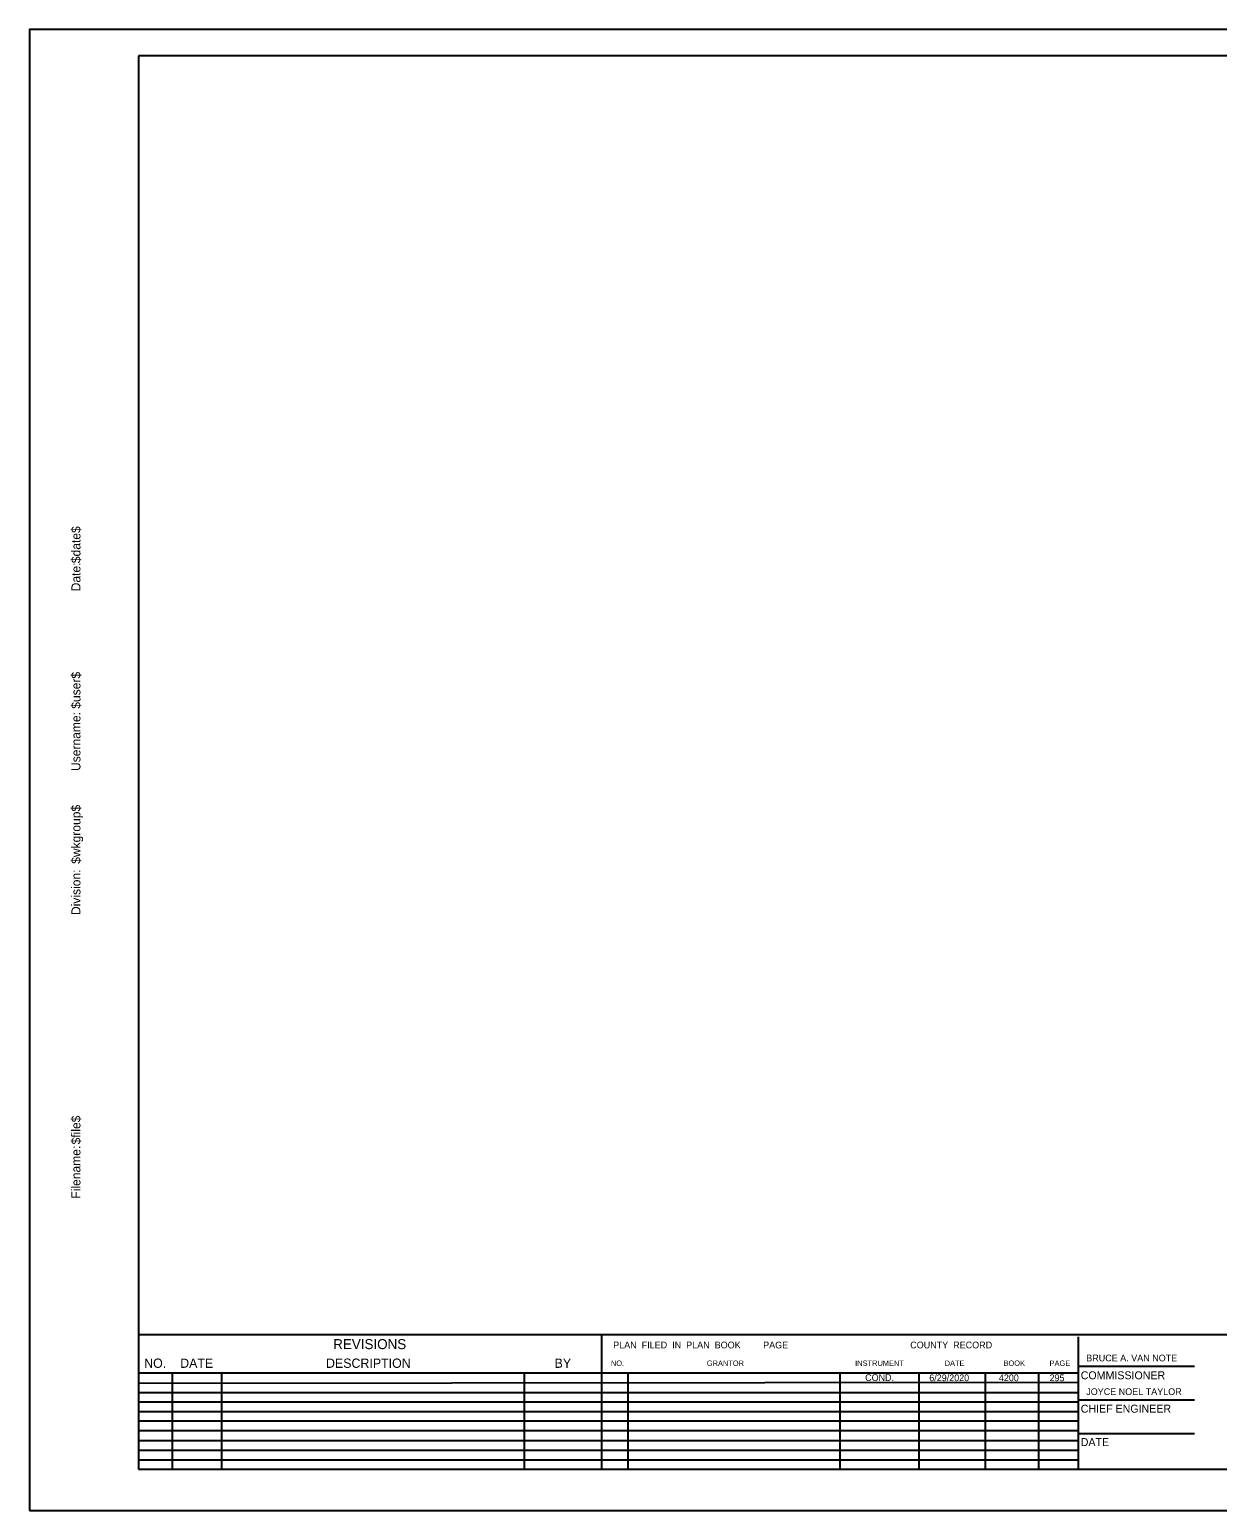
# Model space of a CAD drawing. Extents: x -415 to 435, y -303 to 247.
# Drawn here: x -415 to 26, y -303 to 247 of the extents above; entities that cross this region are included whole.
import ezdxf

# ---------------------------------------------------------------- set-up
doc = ezdxf.new("R2010")
doc.units = 0
for name, color, linetype in [('Border', 7, 'Continuous'), ('EX ROW NOTES', 7, 'Continuous'), ('PLOT BOUNDARY', 7, 'Continuous')]:
    doc.layers.add(name, color=color, linetype=linetype)

msp = doc.modelspace()

# ---------------------------------------------------------------- linework, layer by layer
at = {"layer": 'Border'}
for p, q in [((425, 237.5), (-375, 237.5)), ((-375, 237.5), (-375, -287.5)), ((-375, -237.49), (425, -237.49)), ((-202.99, -237.49), (-202.99, -287.5)), ((-25.83, -238.29), (-25.83, -287.5)), ((-375, -251.67), (-25.83, -251.67)), ((-362.5, -251.67), (-362.5, -287.5)), ((-344.13, -251.67), (-344.13, -287.5)), ((-231.63, -251.67), (-231.63, -287.5)), ((-193.15, -251.67), (-193.15, -287.5)), ((-114.41, -251.67), (-114.41, -287.5)), ((-84.88, -287.5), (-84.88, -251.67)), ((-60.27, -287.5), (-60.27, -251.67)), ((-40.59, -251.67), (-40.59, -287.5)), ((-25.83, -249.2), (17.41, -249.2)), ((-375, -255.6), (-25.83, -255.22)), ((-375, -258.96), (-25.83, -258.96)), ((-375, -262.5), (-26.02, -262.5)), ((-25.83, -261.7), (17.41, -261.7)), ((-375, -266.04), (-25.83, -266.04)), ((-375, -269.59), (-25.83, -269.59)), ((-375, -273.13), (-25.63, -273.13)), ((-25.83, -274.2), (17.41, -274.2)), ((-375, -276.87), (-25.83, -276.87)), ((-375, -280.41), (-25.83, -280.41)), ((-375, -283.96), (-25.83, -283.96)), ((-375, -287.5), (425, -287.5))]:
    msp.add_line(p, q, dxfattribs=at)
at = {"layer": 'PLOT BOUNDARY'}
msp.add_lwpolyline([(-415.47, -302.8), (434.53, -302.8), (434.53, 247.2), (-415.47, 247.2)], close=True, dxfattribs=at)

# ---------------------------------------------------------------- texts
at = {"layer": 'Border'}
for s, height, rotation, p in [('$date$', 3.348, 90, (-396.58, 49.03)), ('Date:', 3.348, 90, (-396.58, 38.58)), ('$user$', 3.348, 90, (-396.58, -5.04)), ('Username:', 3.348, 90, (-396.58, -28.16)), ('$wkgroup$', 3.348, 90, (-396.58, -62.65)), ('Division:', 3.348, 90, (-396.58, -81.67)), ('$file$', 3.348, 90, (-396.58, -166.87)), ('Filename:', 3.348, 90, (-396.58, -187.01)), ('REVISIONS', 3.726, 360, (-302.65, -242.9)), ('NO.', 3.445, 360, (-372.89, -249.85)), ('DATE', 3.445, 360, (-359.52, -249.85)), ('DESCRIPTION', 3.4449, 360, (-305.33, -249.85)), ('BY', 3.445, 360, (-220.38, -249.85)), ('COMMISSIONER', 2.9528, 360, (-24.87, -254.1)), ('CHIEF ENGINEER', 2.9528, 360, (-24.87, -266.5)), ('DATE', 2.953, 360, (-24.87, -278.9))]:
    msp.add_text(s, height=height, rotation=rotation, dxfattribs=at).set_placement(p)
for s, height, p in [('PLAN  FILED  IN  PLAN  BOOK         PAGE', 2.4992, (-198.6, -242.62)), ('COUNTY  RECORD', 2.4992, (-88.23, -242.62)), ('NO.', 2, (-199.45, -249.13)), ('GRANTOR', 2, (-163.82, -249.13)), ('INSTRUMENT', 2, (-108.7, -249.13)), ('DATE', 2, (-75.43, -249.13)), ('BOOK', 2, (-53.58, -249.13)), ('PAGE', 2, (-36.46, -249.13)), ('BRUCE A. VAN NOTE', 2.5, (-22.83, -247.45)), ('JOYCE NOEL TAYLOR', 2.5, (-22.83, -259.95))]:
    msp.add_text(s, height=height, dxfattribs=at).set_placement(p)
at = {"layer": 'EX ROW NOTES'}
for s, p in [('COND.', (-104.97, -254.72)), ('6/29/2020', (-81.15, -254.8)), ('4200', (-55.29, -254.8)), ('295', (-36.46, -254.8))]:
    msp.add_text(s, height=2.49, dxfattribs=at).set_placement(p)

doc.saveas('drawing.dxf')
